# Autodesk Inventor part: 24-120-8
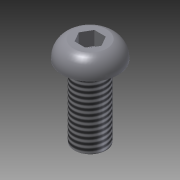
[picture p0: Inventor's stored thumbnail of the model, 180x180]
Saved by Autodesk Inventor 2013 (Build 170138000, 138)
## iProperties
Created: 2004-10
Part Number: 24-120-8
Material: Stahl (hohe Festigk., niedr. Legier.)
Document SubType Name: Modeling
Designer: Autodesk, Inc.
Manufacturer: Standard
Standards Organization: Custom
Description: SCREW, PARKER IPS, BUTTON HEAD, M8X20
Catalog Web Link: http://www.parker.com/ead/cm1.asp?cmid=809
Vendor: PARKER IPS
Mass: 10.8823 g
Surface Area: 9.37524 cm^2
Volume: 1.38805 cm^3
Density: 7.84 g/cm^3
CAGE: 1LJX3
Dept. ID: Product Design
Description #2: ---
Finish #1: ---
Finish #2: ---
Material ID: ---
Project Number: ---
Author: Autodesk, Inc.
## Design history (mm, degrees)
derived "2X-YYY-ZZ IPS Screws.ipt"
body "Solid1"
tag "TaggingFeature2"
feature "Solid1::2X-YYY-ZZ IPS Screws.ipt" dims "ScaleForDerivedMember" = 10
